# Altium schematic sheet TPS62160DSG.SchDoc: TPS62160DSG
size 296 x 210 mm; Revision: 1.0; DocumentSize: A4
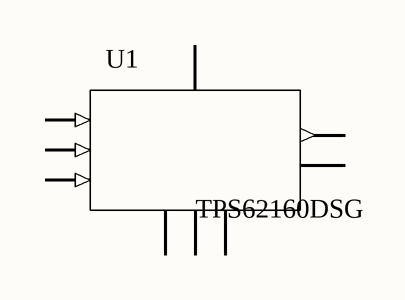
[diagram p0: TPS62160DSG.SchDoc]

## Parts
U1  value TPS62160DSG

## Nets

Not connected (* = marked no-connect by the designer): U1 1(PGND) 2(VIN) 3(EN) 4(AGND) 5(FB) 6(VOS) 7(SW) 8(PG) 9(EP)

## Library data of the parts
U1 = TPS62160DSG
